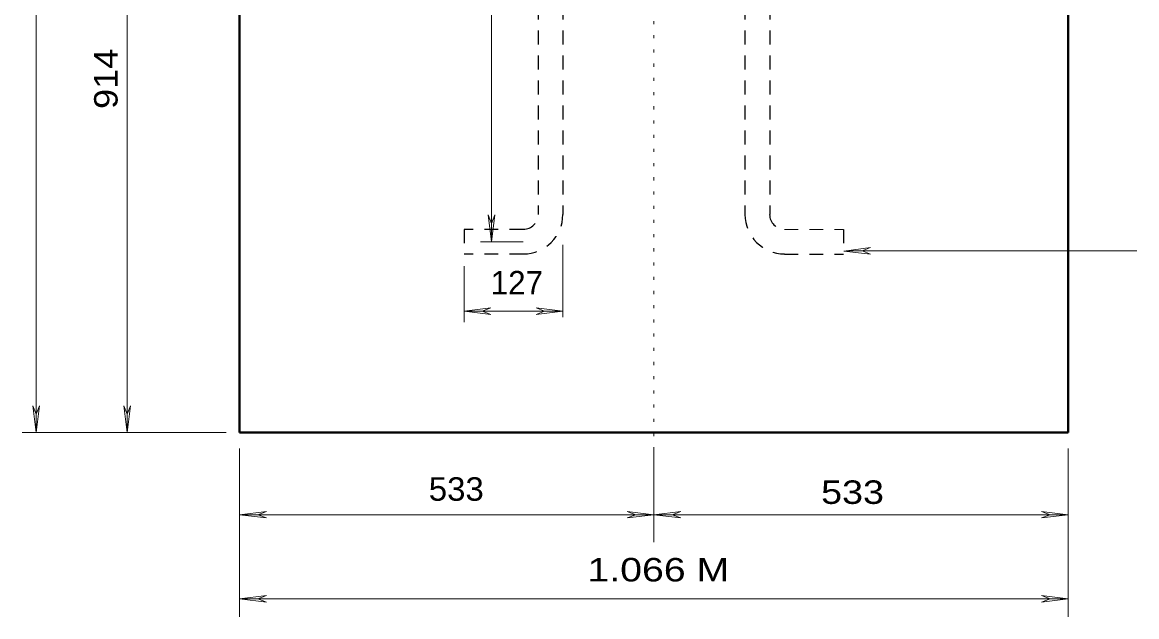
# Model space of a CAD drawing. Extents: x 312583 to 312854, y 144419 to 144597.
# Drawn here: x 312625.03 to 312661.12, y 144464.6 to 144483.85 of the extents above; entities that cross this region are included whole.
import ezdxf

# ---------------------------------------------------------------- set-up
doc = ezdxf.new("R2010")
doc.units = 0
doc.header["$LTSCALE"] = 0.3
doc.linetypes.add('DOTTED', pattern=[1.5, 0.3, -1.2])
doc.linetypes.add('SHORT_DASHED', pattern=[2.7, 1.5, -1.2])
doc.layers.add('1', color=7, linetype='Continuous', lineweight=25)
doc.layers.add('2', color=7, linetype='Continuous', lineweight=13)

msp = doc.modelspace()

# ---------------------------------------------------------------- linework, layer by layer
at = {"layer": '1', "linetype": 'DOTTED', "lineweight": 13}
msp.add_line((312645.488, 144469.9913), (312645.488, 144502.8813), dxfattribs=at)
at = {"layer": '1', "linetype": 'SHORT_DASHED'}
for p, q in [((312641.739, 144499.784), (312641.739, 144477.6273)), ((312642.5363, 144499.784), (312642.5363, 144477.6273)), ((312648.432, 144499.784), (312648.432, 144477.6273)), ((312649.237, 144499.784), (312649.237, 144477.6273)), ((312641.256, 144477.1443), (312639.3393, 144477.1443)), ((312639.3393, 144477.1443), (312639.3393, 144476.347)), ((312651.629, 144477.1443), (312651.629, 144476.347)), ((312641.256, 144476.347), (312639.3393, 144476.347)), ((312649.7123, 144476.347), (312651.629, 144476.347))]:
    msp.add_line(p, q, dxfattribs=at)
at = {"layer": '1', "lineweight": 40}
for p, q in [((312632.0713, 144493.5663), (312632.0713, 144470.5663)), ((312658.9047, 144493.5663), (312658.9047, 144470.5663)), ((312632.0713, 144470.5663), (312658.9047, 144470.5663))]:
    msp.add_line(p, q, dxfattribs=at)
at = {"layer": '1', "linetype": 'SHORT_DASHED', "lineweight": 13}
msp.add_line((312649.7123, 144477.1443), (312651.629, 144477.1443), dxfattribs=at)
at = {"layer": '1', "linetype": 'SHORT_DASHED'}
for centre, radius, start, end in [((312641.2592, 144477.6267), 1.2778, 270, 0), ((312641.2592, 144477.6267), 0.4792, 270, 0), ((312649.713, 144477.6267), 1.2778, 180, 270), ((312649.713, 144477.6267), 0.4792, 180, 270)]:
    msp.add_arc(centre, radius, start, end, dxfattribs=at)
at = {"layer": '2'}
for p, q in [((312625.478, 144470.5663), (312625.478, 144501.233)), ((312640.2287, 144499.784), (312640.2287, 144476.7457)), ((312640.1213, 144477.612), (312640.2287, 144477.336)), ((312640.2287, 144476.7457), (312640.1213, 144477.612)), ((312640.336, 144477.612), (312640.2287, 144477.336)), ((312640.2287, 144476.7457), (312640.336, 144477.612)), ((312641.256, 144476.7457), (312639.876, 144476.7457)), ((312642.5363, 144476.646), (312642.5363, 144474.3)), ((312651.6367, 144476.439), (312652.503, 144476.5617)), ((312652.503, 144476.5617), (312652.227, 144476.4467)), ((312651.6367, 144476.439), (312652.503, 144476.347)), ((312661.1203, 144476.4467), (312651.721, 144476.4467)), ((312652.503, 144476.347), (312652.227, 144476.4467)), ((312639.3393, 144475.9483), (312639.3393, 144474.139)), ((312639.3393, 144474.4917), (312640.2057, 144474.599)), ((312639.3393, 144474.4917), (312642.5363, 144474.4917)), ((312639.3393, 144474.4917), (312640.2057, 144474.3843)), ((312640.2057, 144474.599), (312639.9297, 144474.4917)), ((312640.2057, 144474.3843), (312639.9297, 144474.4917)), ((312641.67, 144474.599), (312641.946, 144474.4917)), ((312642.5363, 144474.4917), (312641.67, 144474.599)), ((312641.67, 144474.3843), (312641.946, 144474.4917)), ((312642.5363, 144474.4917), (312641.67, 144474.3843)), ((312625.3707, 144471.4327), (312625.478, 144471.1567)), ((312625.478, 144470.5663), (312625.3707, 144471.4327)), ((312625.5853, 144471.4327), (312625.478, 144471.1567)), ((312625.478, 144470.5663), (312625.5853, 144471.4327)), ((312628.3223, 144471.4327), (312628.4297, 144471.1567)), ((312628.4297, 144470.5663), (312628.3223, 144471.4327)), ((312628.537, 144471.4327), (312628.4297, 144471.1567)), ((312628.4297, 144470.5663), (312628.537, 144471.4327)), ((312631.6343, 144470.5663), (312625.0333, 144470.5663)), ((312632.0713, 144470.0527), (312632.0713, 144464.6017)), ((312645.488, 144469.9913), (312645.488, 144467.0167)), ((312658.9047, 144470.0527), (312658.9047, 144464.6017)), ((312632.0713, 144467.906), (312632.9377, 144468.0133)), ((312632.0713, 144467.906), (312632.9377, 144467.7987)), ((312632.9377, 144468.0133), (312632.6617, 144467.906)), ((312632.9377, 144467.7987), (312632.6617, 144467.906)), ((312644.6217, 144468.0133), (312644.8977, 144467.906)), ((312645.488, 144467.906), (312644.6217, 144468.0133)), ((312644.6217, 144467.7987), (312644.8977, 144467.906)), ((312645.488, 144467.906), (312644.6217, 144467.7987)), ((312645.488, 144467.906), (312646.3543, 144468.0133)), ((312645.488, 144467.906), (312646.3543, 144467.7987)), ((312646.3543, 144468.0133), (312646.0783, 144467.906)), ((312646.3543, 144467.7987), (312646.0783, 144467.906)), ((312658.0383, 144468.0133), (312658.3143, 144467.906)), ((312658.9047, 144467.906), (312658.0383, 144468.0133)), ((312658.0383, 144467.7987), (312658.3143, 144467.906)), ((312658.9047, 144467.906), (312658.0383, 144467.7987)), ((312632.0713, 144465.1843), (312632.9377, 144465.2917)), ((312632.9377, 144465.2917), (312632.6617, 144465.1843)), ((312658.0383, 144465.2917), (312658.3143, 144465.1843)), ((312658.9047, 144465.1843), (312658.0383, 144465.2917)), ((312632.0713, 144465.1843), (312658.9047, 144465.1843)), ((312632.0713, 144465.1843), (312632.9377, 144465.077)), ((312632.9377, 144465.077), (312632.6617, 144465.1843)), ((312658.0383, 144465.077), (312658.3143, 144465.1843)), ((312658.9047, 144465.1843), (312658.0383, 144465.077))]:
    msp.add_line(p, q, dxfattribs=at)
for points in [[(312628.4297, 144470.5663), (312628.4297, 144493.5663), (312628.4297, 144501.233)], [(312632.0713, 144467.906), (312645.488, 144467.906), (312658.9047, 144467.906)]]:
    msp.add_lwpolyline(points, dxfattribs=at)

# ---------------------------------------------------------------- texts
at = {"layer": '2', "width": 1.15}
msp.add_text('914 ', height=0.76, rotation=90, dxfattribs=at).set_placement((312628.1191, 144481.0437))
at = {"layer": '2'}
msp.add_text('127', height=0.76, dxfattribs=at).set_placement((312640.2005, 144475.0383))
for s, width, p in [('533', 1.05, (312638.196, 144468.3575)), ('533 ', 1.2, (312650.9005, 144468.255)), ('1.066 M', 1.25, (312643.3348, 144465.7441))]:
    msp.add_text(s, height=0.76, dxfattribs=dict(at, width=width)).set_placement(p)

doc.saveas('drawing.dxf')
